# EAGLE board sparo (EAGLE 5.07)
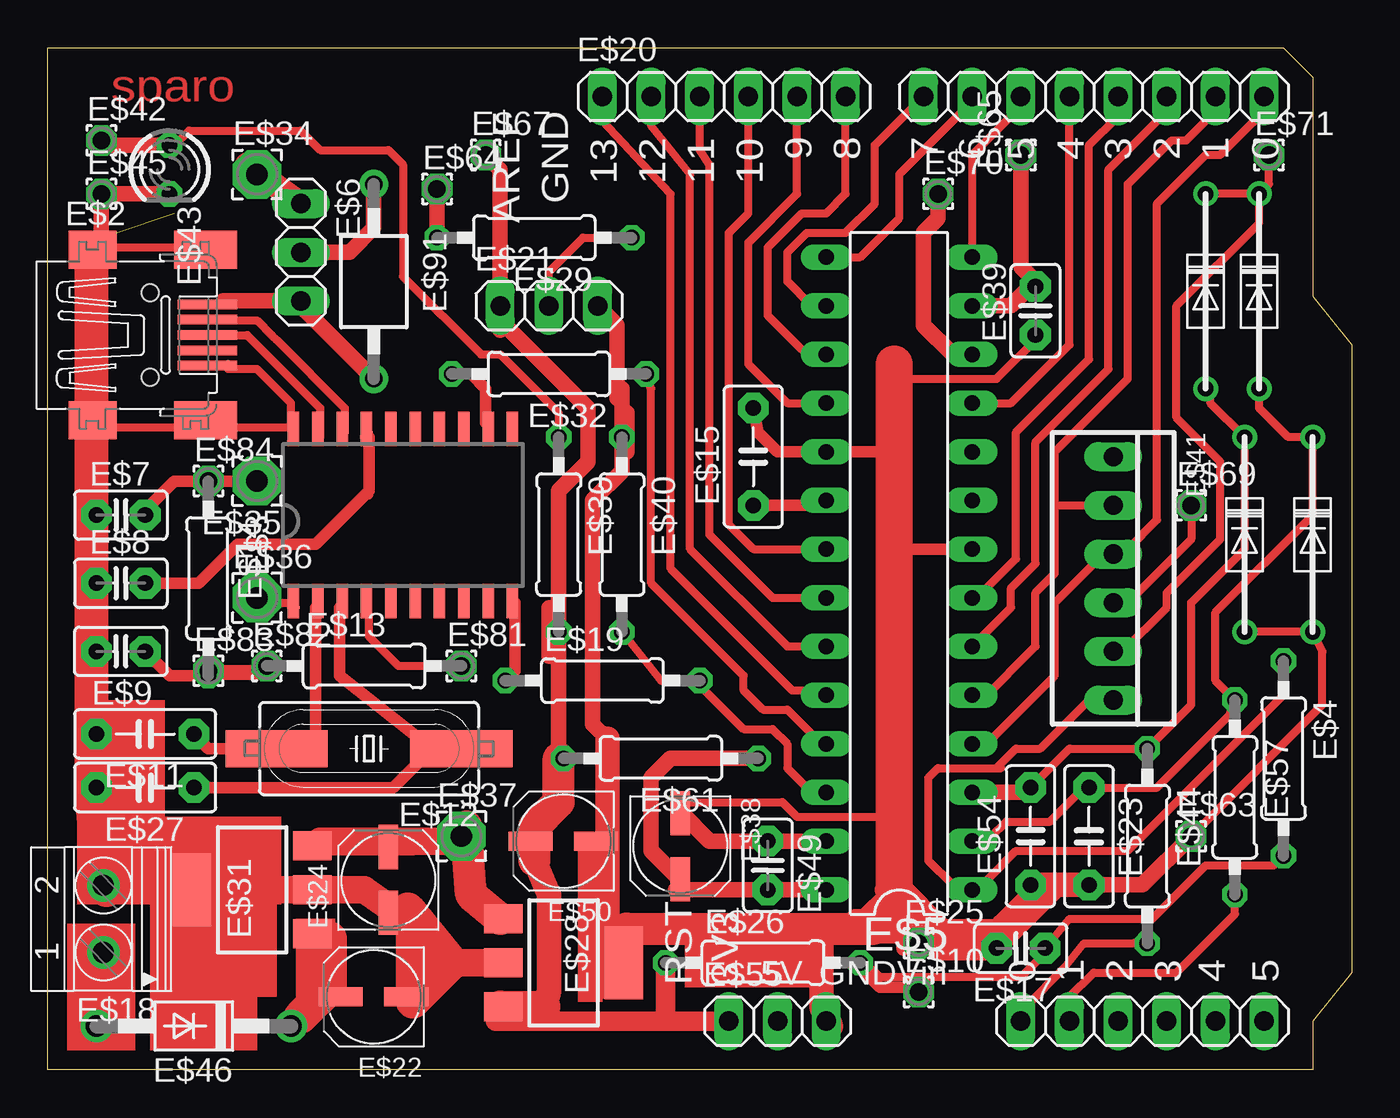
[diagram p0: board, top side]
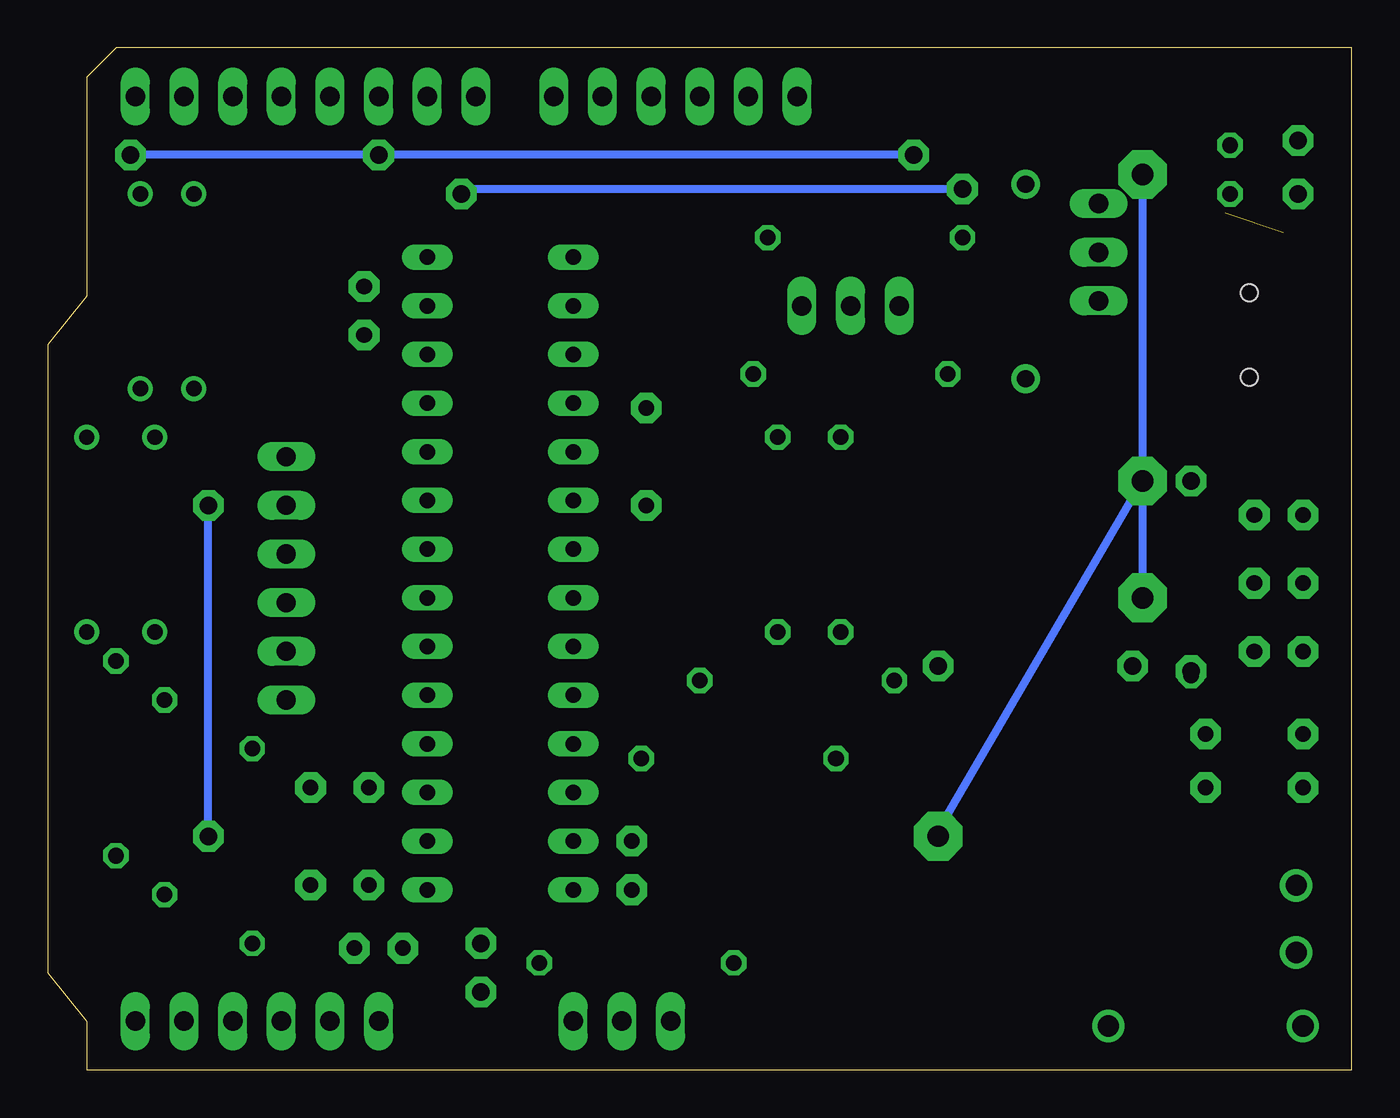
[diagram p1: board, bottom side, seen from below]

Size 68.07 x 53.34 mm. Coordinates in mm from the lower left corner, seen from the top.
Outline: 0,53.34 64.52,53.34 66.04,51.82 66.04,40.39 68.07,37.85 68.07,5.08 66.04,2.54 66.04,0 0,0 0,53.34
Copper layers (1*16): Top 0.035mm / dielectric 1.5mm / Bottom 0.035mm
Design rules "default": minimum track width 10mil, minimum drill 24mil, track to track 8mil, track to pad 8mil, pad to pad 8mil, via to via 8mil, smd to smd 8mil, copper to edge 40mil, drill to drill 8mil, minimum pad ring 10mil, minimum via ring 8mil, stop-mask expansion 4mil, vias tented up to drill 0mil, thermal gap 10mil

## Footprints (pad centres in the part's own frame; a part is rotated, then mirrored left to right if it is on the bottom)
32005-201 = smd 3.1 x 0.5: 1 3,1.6; 2 3,0.8; 3 3,0; 4 3,-0.8; 5 3,-1.6 | smd 2.5 x 2: M1 -3,-4.45; M2 -3,4.45 | smd 3.3 x 2: M3 2.9,4.45; M4 2.9,-4.45 | hole 0.9: 0,2.2; 0,-2.2
SOP20 = smd 0.6 x 1.8: 1 -5.715,-4.475; 2 -4.445,-4.475; 3 -3.175,-4.475; 4 -1.905,-4.475; 5 -0.635,-4.475; 6 0.635,-4.475; 7 1.905,-4.475; 8 3.175,-4.475; 9 4.445,-4.475; 10 5.715,-4.475; 11 5.715,4.5; 12 4.445,4.5; 13 3.175,4.5; 14 1.905,4.5; 15 0.635,4.5; 16 -0.635,4.5; 17 -1.905,4.5; 18 -3.175,4.5; 19 -4.445,4.5; 20 -5.715,4.5
0207/10 = drill 0.813 octagon: 1 -5.08,0; 2 5.08,0
DIL28-3 = drill 0.813 long: 1 -16.51,-3.81; 2 -13.97,-3.81; 3 -11.43,-3.81; 4 -8.89,-3.81; 5 -6.35,-3.81; 6 -3.81,-3.81; 7 -1.27,-3.81; 8 1.27,-3.81; 9 3.81,-3.81; 10 6.35,-3.81; 11 8.89,-3.81; 12 11.43,-3.81; 13 13.97,-3.81; 14 16.51,-3.81; 15 16.51,3.81; 16 13.97,3.81; 17 11.43,3.81; 18 8.89,3.81; 19 6.35,3.81; 20 3.81,3.81; 21 1.27,3.81; 22 -1.27,3.81; 23 -3.81,3.81; 24 -6.35,3.81; 25 -8.89,3.81; 26 -11.43,3.81; 27 -13.97,3.81; 28 -16.51,3.81
1X03 = drill 1.016 long: 1 -2.54,0; 2 0,0; 3 2.54,0
C2.5-2 = drill 0.813 pad 1.6 octagon: 1 -1.27,0; 2 1.27,0
1,6/0,9 = drill 0.914 pad 1.6 octagon: 1 0,0
C5B2.5 = drill 0.813 pad 1.6 octagon: 1 -2.54,0; 2 2.54,0
HC49UP = smd 5.334 x 1.93: 1 -4.826,0; 2 4.826,0
C5B3 = drill 0.813 pad 1.6 octagon: 1 -2.54,0; 2 2.54,0
1751248 = drill 1.1 pad 1.7 round: 1 -1.75,-0.1; 2 1.75,-0.1
1X06 = drill 1.016 long: 1 -6.35,0; 2 -3.81,0; 3 -1.27,0; 4 1.27,0; 5 3.81,0; 6 6.35,0
UD-5X5,8_NICHICON = smd 2.3 x 1: + 1.725,0; - -1.7,0
SOT223 = smd 1.5 x 2: 1 -2.3,-3.15; 2 0,-3.15; 3 2.3,-3.15 | smd 3.8 x 2: 4 0,3.15
DS10 = drill 0.8 round: P$1 -5.08,0; P$2 5.08,0
2,54/1,1 = drill 1.118 pad 2.54 octagon: 1 0,0
22-23-2061 = drill 1 long: 1 -6.35,0; 2 -3.81,0; 3 -1.27,0; 4 1.27,0; 5 3.81,0; 6 6.35,0
LED3MM = drill 0.813 octagon: A -1.27,0; K 1.27,0
DO41-10 = drill 1.118 round: A 5.08,0; C -5.08,0
BL01RN1A = drill 0.9 pad 1.5 round: 1 -5.08,0; 2 5.08,0
1X08 = drill 1.016 long: 1 -8.89,0; 2 -6.35,0; 3 -3.81,0; 4 -1.27,0; 5 1.27,0; 6 3.81,0; 7 6.35,0; 8 8.89,0

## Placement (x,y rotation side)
E$2  [32005-201]  5.33,38.35 0 top
E$3  [SOP20]  18.54,28.96 0 top
E$4  [0207/10]  64.52,16.26 270 top
E$5  [DIL28-3]  44.45,25.91 90 top
E$6  [1X03]  13.21,42.67 270 top
E$7  [C2.5-2]  3.81,28.96 0 top
E$8  [C2.5-2]  3.81,25.4 0 top
E$9  [C2.5-2]  3.81,21.84 180 top
E$10  [1,6/0,9]  45.47,4.06 0 top
E$11  [C5B2.5]  5.08,17.53 180 top
E$12  [HC49UP]  16.76,16.76 180 top
E$13  [0207/10]  16.51,21.08 0 top
E$14  [0207/10]  8.38,25.65 270 top
E$15  [C5B3]  36.83,32 90 top
E$17  [C2.5-2]  50.8,6.35 180 top
E$18  [1751248]  2.79,7.87 90 top
E$19  [0207/10]  28.96,20.32 0 top
E$20  [1X06]  35.31,50.8 0 top
E$21  [1X03]  26.16,39.88 0 top
E$22  [UD-5X5,8_NICHICON]  17.02,3.81 180 top
E$23  [C5B2.5]  54.36,12.19 270 top
E$24  [UD-5X5,8_NICHICON]  17.78,9.91 90 top
E$25  [1,6/0,9]  45.47,6.6 0 top
E$26  [0207/10]  37.34,5.59 0 top
E$27  [C5B2.5]  5.08,14.73 180 top
E$28  [SOT223]  26.92,5.59 270 top
E$29  [0207/10]  25.4,43.43 180 top
E$30  [0207/10]  26.67,27.94 270 top
E$31  [SOT223]  10.67,9.4 90 top
E$32  [0207/10]  26.16,36.32 180 top
E$33  [DS10]  63.25,40.64 90 top
E$34  [2,54/1,1]  10.92,46.74 0 top
E$35  [2,54/1,1]  10.92,30.73 180 top
E$36  [2,54/1,1]  10.92,24.64 0 top
E$37  [2,54/1,1]  21.59,12.19 0 top
E$38  [UD-5X5,8_NICHICON]  33.02,11.68 270 top
E$39  [C2.5-2]  51.56,39.62 90 top
E$40  [0207/10]  29.97,27.94 270 top
E$41  [22-23-2061]  55.63,25.65 270 top
E$42  [1,6/0,9]  2.79,48.51 0 top
E$43  [LED3MM]  6.35,46.99 270 top
E$44  [0207/10]  57.4,11.68 270 top
E$45  [1,6/0,9]  2.79,45.72 0 top
E$46  [DO41-10]  7.62,2.29 180 top
E$49  [C2.5-2]  37.59,10.67 270 top
E$50  [UD-5X5,8_NICHICON]  26.92,11.94 180 top
E$51  [DS10]  66.04,27.94 90 top
E$52  [DS10]  60.45,40.64 90 top
E$53  [DS10]  62.48,27.94 90 top
E$54  [C5B2.5]  51.31,12.19 90 top
E$55  [1X03]  38.1,2.54 0 top
E$57  [0207/10]  61.98,14.22 270 top
E$61  [0207/10]  32,16.26 180 top
E$63  [1,6/0,9]  59.69,12.19 0 top
E$64  [1,6/0,9]  20.32,45.97 0 top
E$65  [1,6/0,9]  50.8,47.75 90 top
E$67  [1,6/0,9]  22.86,47.75 0 top
E$69  [1,6/0,9]  59.69,29.46 0 top
E$70  [1,6/0,9]  46.48,45.72 0 top
E$71  [1,6/0,9]  63.75,47.75 0 top
E$81  [1,6/0,9]  21.59,21.08 0 top
E$82  [1,6/0,9]  11.43,21.08 0 top
E$83  [1,6/0,9]  8.38,20.83 0 top
E$84  [1,6/0,9]  8.38,30.73 0 top
E$91  [BL01RN1A]  17.02,41.15 270 top
U$2  ANALOG  [1X06]  57.15,2.54 0 top
U$3  DIGITAL_0_7  [1X08]  54.61,50.8 0 top

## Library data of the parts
E$2 = con-cypressindustries
E$3 = holtek
E$4 E$13 E$14 E$19 E$26 E$29 E$30 E$32 E$40 E$44 E$57 E$61 = resistor
E$5 = microchip
E$6 E$20 E$21 E$55 = pinhead
E$7-E$9 E$11 E$15 E$17 E$23 E$27 E$39 E$49 E$54 = capacitor-wima
E$10 E$25 E$34-E$37 E$42 E$45 E$63-E$65 E$67 E$69-E$71 E$81-E$84 = wirepad
E$12 = crystal
E$18 = con-phoenix-350
E$22 E$24 E$38 E$50 = rcl
E$28 E$31 = v-reg
E$33 E$51-E$53 = hydr
E$41 = con-molex
E$43 = led
E$46 = diode
E$91 = inductors
U$2 U$3 = arduino

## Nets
S$3: E$5.15
S$4: E$57.2
S$7: E$71.1
S$10: E$41.6
S$11: E$5.16 U$3.1
S$12: E$5.18
S$15: E$5.19 E$15.2
S$16: E$5.22 E$20.3
S$17: E$20.1
S$18: E$5.23 E$20.2
S$19: E$55.1
S$20: U$3.7
S$22: E$8.2
S$24: E$5.21
S$25: E$5.14
S$26: E$6.3 E$91.2
S$27: E$11.1
S$28: E$26.1
S$29: E$21.2 E$29.1
S$30: E$32.2
S$31: E$23.1
S$32: U$3.8
S$34: E$34.1 E$35.1
S$36: E$61.1
S$39: E$5.12 E$70.1
S$40: E$29.2 E$64.1
S$41: E$5.3 E$54.2
S$42: E$19.1
S$49: E$5.6
S$50: E$5.13
S$51: E$32.1
S$53: E$9.1 E$13.1
S$54: E$27.1
S$55: E$5.28 E$49.2
S$56: E$21.1 E$65.1 E$67.1
S$57: E$69.1
S$61: E$6.2 E$91.1
S$63: E$6.1
S$68: E$21.3
S$70: E$5.11 U$3.4
S$71: E$13.2
S$74: E$5.27
S$81: E$30.1
S$85: E$4.2
S$89: E$44.2
S$90: E$57.1
S$92: E$4.1
S$94: E$40.2
S$95: E$17.2 E$54.1
S$99: E$25.1
S$100: E$17.1
S$103: E$26.2

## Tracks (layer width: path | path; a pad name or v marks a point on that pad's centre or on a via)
S$1
  Top 0.406: 63.75,50.29 61.21,47.75 60.45,47.75 57.91,45.21 57.91,28.7 56.39,27.18
S$2
  Top 0.61: 13.97,24.13 13.97,17.53
S$3
  Top 0.406: E$5.15 42.42,42.42 44.45,44.45 44.45,46.74 48.26,50.55
S$4
  Top 0.406: 53.34,3.81 54.61,5.08 58.93,5.08 61.98,8.13 E$57.2
S$5
  Top 0.61: 42.42,5.33 43.43,4.32 45.72,4.32
S$6
  Top 0.813: 29.21,17.27 28.45,18.03 28.45,29.72 29.97,31.24 29.97,35.56
  Top 1.27: 29.21,4.32 29.21,17.27
S$7
  Top 0.406: E$71.1 63.75,46.23 63.25,45.72 | 63.25,45.72 63.25,45.97 | 63.25,45.72 60.71,45.72 | 63.25,45.72 63.25,44.2 58.93,39.88 58.93,34.04 61.21,31.75 61.21,27.69 58.42,24.89 58.42,24.13 56.13,21.84
S$8
  Top 0.406: 8.89,42.93 2.54,42.93 2.29,42.67
S$9
  Top 0.406: 55.88,49.78 54.36,48.26 54.36,37.08 50.55,33.27 50.55,26.67 48.77,24.89
S$10
  Top 0.406: 47.24,9.65 45.97,10.92 45.97,15.24 46.48,15.75 49.53,15.75 | 49.53,15.75 49.78,15.75 | 49.53,15.75 50.55,16.76 51.82,16.76 54.36,19.3 E$41.6
S$11
  Top 0.406: E$5.16 39.88,39.88 38.61,41.15 38.61,42.67 39.62,43.69 41.66,43.69 43.18,45.21 43.18,48.26 U$3.1 43.94,49.02
S$12
  Top 0.406: 39.12,50.8 39.12,45.72 36.58,43.18 36.58,36.83 38.61,34.8 E$5.18
S$13
  Top 0.406: 44.45,27.18 44.45,27.69
  Top 0.61: 44.45,27.18 48.51,27.18
S$14
  Top 0.305: 40.89,37.59 41.15,37.59
  Top 0.406: 41.66,50.55 41.66,45.72 40.64,44.7 39.37,44.7 37.59,42.93 37.59,39.37 39.37,37.59 40.89,37.59
S$15
  Top 0.406: E$5.19 44.45,32.26
  Top 0.61: E$15.2 37.08,33.27 38.1,32.26 E$5.19 43.69,32.26 43.94,32.51
S$16
  Top 0.406: E$5.22 37.85,24.64 34.54,27.94 34.54,47.24 34.04,48.01 E$20.3
S$17
  Top 0.406: 40.64,19.81 38.86,19.81 32.51,26.16 32.51,45.72 28.96,49.53 E$20.1
S$18
  Top 0.406: E$20.2 31.5,49.28 33.53,46.74 33.53,27.18 38.61,22.1 E$5.23
S$19
  Top 1.016: 23.37,2.54 E$55.1
S$20
  Top 0.406: 48.77,19.3 51.56,22.1 51.56,24.89 52.58,25.91 52.58,32.26 56.39,36.07 56.39,46.23 58.67,48.51 59.44,48.51 59.69,48.77 60.2,49.28 60.96,50.04 | 60.96,49.78 60.96,50.04 | U$3.7 60.96,50.55 60.96,50.04
S$21
  Top 0.61: 2.03,11.94 2.54,11.43
  Top 1.778: 2.29,14.48 2.29,42.93 | 2.29,14.48 2.54,14.48 | 2.54,11.43 2.29,14.48
S$22
  Top 0.406: 16.51,33.02 16.76,33.27 16.76,33.02 16.76,29.97
  Top 0.61: 16.76,33.02 16.76,30.23 13.97,27.43 9.91,27.43 7.87,25.4 E$8.2
S$23
  Top 0.406: 12.95,24.13 12.7,24.13 12.7,24.38 10.67,24.38
S$24
  Top 0.305: 35.56,42.16 35.56,34.8
  Top 0.406: 36.58,50.8 36.58,44.7 35.56,43.69 35.56,42.16 35.56,28.45 36.83,27.18 E$5.21
S$25
  Top 0.406: 50.8,50.29 48.26,47.75 E$5.14
S$26
  Top 0.813: 9.14,40.13 E$6.3 13.21,39.88 E$91.2
S$27
  Top 0.61: 13.97,17.02 14.22,16.76 8.38,16.76 E$11.1
S$28
  Top 1.016: 32.26,2.79 E$26.1
S$29
  Top 0.406: E$21.2 26.16,41.66 27.94,43.43 E$29.1
S$30
  Top 0.61: 22.86,33.78 22.86,35.56 22.1,36.32 E$32.2
S$31
  Top 0.406: 49.28,12.19 50.04,12.95 52.32,12.95 54.1,14.73 E$23.1
S$32
  Top 0.406: U$3.8 63.5,50.04 62.23,48.77
S$33
  Top 1.778: 14.73,6.86 14.73,4.32 13.21,2.79
S$34
  Bottom 0.406: 21.59,12.45 E$35.1 | E$35.1 10.92,24.38 | E$34.1 E$35.1
S$35
  Top 1.676: 30.23,7.37 43.18,7.37 44.2,8.38
S$36
  Top 0.813: E$61.1 32.51,16.26 31.5,15.24 31.5,11.68 31.5,11.43 33.02,9.91
S$37
  Top 0.406: 52.58,29.46 55.63,29.46
S$38
  Top 1.778: 2.54,12.19 2.54,11.94 3.05,9.4
S$39
  Top 0.813: E$5.12 47.24,37.34 45.72,38.86 45.72,43.69 46.48,44.45 E$70.1
S$40
  Top 0.813: E$29.2 E$64.1
  Bottom 0.406: E$64.1 46.48,45.97
S$41
  Top 0.406: 57.4,16.76 53.34,16.76 52.32,15.75 51.82,15.24 E$54.2
  Top 0.813: E$5.3 51.05,14.48 E$54.2
S$42
  Top 0.61: 24.38,24.38 24.38,20.83 E$19.1
S$43
  Top 1.27: 40.39,7.11 40.39,3.3 40.89,2.29
S$44
  Top 0.813: 2.54,45.72 6.6,45.72
S$46  (1 unrouted)
S$47
  Top 0.406: 54.61,26.42 52.58,24.38 52.58,20.57 49.02,17.02
S$48
  Top 0.406: 45.21,36.07 49.53,36.07 51.82,38.35
S$49
  Top 0.406: 58.42,50.04 55.37,46.99 55.37,36.58 51.56,32.77 51.56,26.42 50.29,25.15 50.29,24.13 E$5.6
S$50
  Top 0.813: 51.31,40.89 50.29,39.88 E$5.13
S$51
  Top 0.406: E$32.1 31.5,35.56 31.5,25.4 36.32,20.57 36.32,19.81 37.34,18.8 38.61,18.8 40.39,17.02
S$52
  Top 0.406: 44.2,8.13 43.94,7.62
S$53
  Top 0.406: E$13.1 10.92,20.57 8.38,20.57
  Top 0.61: E$9.1 6.35,20.57 8.38,20.57 8.64,20.83 11.43,20.83
S$54
  Top 0.61: E$27.1 18.03,14.73 19.56,16.26
S$55
  Top 0.813: E$5.28 E$49.2 32.77,9.4
S$56
  Top 0.813: 51.82,40.89 50.8,41.91 E$65.1 | E$67.1 23.62,46.99 E$21.1 | E$21.1 23.62,38.61 | E$21.1 23.62,40.13 | E$21.1 23.62,39.12 28.19,34.54 28.19,31.75 26.67,30.23 26.67,16.26
  Top 1.27: 25.4,10.92 26.16,9.14 26.16,4.06 25.91,3.3
  Top 1.676: 26.67,16.26 26.67,13.97 25.4,12.7 25.4,10.92 | 23.62,3.3 25.91,3.3
  Bottom 0.406: 64.01,47.75 E$65.1 E$67.1
S$57
  Top 0.406: 56.64,24.38 56.64,24.64 59.69,27.69 E$69.1
  Bottom 0.406: 59.69,12.19 E$69.1
S$58
  Top 0.406: 14.73,7.11 14.48,6.86
S$59
  Top 0.406: 19.05,11.68 19.3,11.68
  Top 1.016: 14.48,11.68 19.05,11.68
S$60
  Top 0.61: 11.94,16.76 13.72,17.02
S$61
  Top 0.813: E$91.1 17.02,43.94 15.75,42.67 E$6.2
S$62
  Top 0.61: 15.24,24.13 15.24,20.57 20.07,16.76
S$63
  Top 1.27: E$6.1 10.41,47.24
S$64
  Top 0.406: 2.03,33.53 9.4,33.53 9.14,33.78
S$65
  Top 0.406: 12.7,33.53 12.7,34.8 11.43,36.07 10.92,36.58 9.4,36.58 9.4,36.83 | 12.7,33.53 12.7,32.77 | 9.65,33.53 12.7,33.53
S$66
  Top 0.406: 14.22,33.02 14.22,34.54 10.41,38.35 9.4,38.35
S$67
  Top 0.406: 15.49,33.27 15.49,34.54 11.94,38.1 11.68,38.35 10.92,39.12 9.65,39.12
S$68
  Top 0.813: 29.46,39.12 E$21.3 29.72,38.86 29.72,35.05
S$69
  Top 1.422: 14.22,11.94 21.84,11.94
S$70
  Top 0.406: E$5.11 50.29,34.8 53.34,37.85 U$3.4
S$71
  Top 0.406: 16.76,23.62 16.76,22.61 18.29,21.08 E$13.2
S$72
  Top 0.406: 10.92,30.73 9.14,30.73
  Top 0.61: 4.83,28.96 6.6,30.73 10.92,30.73
S$73
  Top 0.406: 2.29,42.42 2.54,42.67 | 2.29,34.04 2.54,33.78
  Top 0.813: 2.29,34.04 2.29,42.42
S$74
  Top 0.813: E$5.27 34.54,11.94 33.02,13.46
S$75
  Top 0.813: 26.16,24.13 26.16,21.59
S$76
  Top 1.676: 21.84,12.7 22.1,9.14 23.62,7.87
S$77
  Top 0.406: 43.43,13.21 39.12,13.21 38.35,13.97 33.02,13.97
S$78
  Top 0.406: 51.05,3.3 53.09,5.33 54.1,6.6 57.66,6.6
S$79
  Top 0.813: 30.23,34.29 30.23,32.26
S$80
  Top 0.61: 40.89,29.72 39.88,29.46 36.83,29.46
S$81
  Top 0.406: E$30.1 26.67,34.29 23.62,37.34 22.61,37.34 18.54,41.4 18.54,47.24 17.78,48.01 14.22,48.01 13.21,49.02 7.37,49.02 6.6,48.26
S$82
  Top 0.406: 8.13,8.89 8.38,9.14
S$83
  Top 1.016: 43.43,7.37 50.29,7.37
S$84
  Top 1.422: 21.08,5.59 23.37,5.59 | 19.05,7.62 16.51,9.4 9.14,9.4
  Top 1.778: 18.8,8.38 21.08,5.59 19.05,3.56 19.05,7.62
S$85
  Top 0.406: 53.59,7.87 57.66,7.87 60.45,10.67 64.01,10.67 E$4.2
S$86
  Top 0.813: 2.79,48.26 6.35,48.26
S$87
  Top 0.406: 2.29,18.03 2.54,18.29
S$88
  Top 0.406: 8.64,8.89 8.89,8.89
S$89
  Top 0.406: E$44.2 56.64,6.6
S$90
  Top 0.406: 63.25,35.81 63.25,34.54 64.77,33.02 66.04,33.02 66.04,28.96 60.96,23.88 60.96,20.32 E$57.1 61.72,18.54 57.91,14.73 54.61,14.73
S$91
  Top 1.016: 49.78,7.62 51.56,9.4
S$92
  Top 0.406: 49.02,9.91 50.55,11.43 56.39,11.43 64.52,19.56 E$4.1
S$93
  Top 0.813: 2.79,43.43 2.79,44.96
S$94
  Top 0.406: 39.88,14.48 38.61,15.75 38.61,17.02 37.85,17.78 36.32,17.78 33.78,20.32 32,20.32 E$40.2
S$95
  Top 0.406: 62.48,22.86 66.04,22.86 66.55,21.84 66.55,19.05 59.69,12.19
  Top 0.813: 59.69,12.19 57.15,9.65 54.36,9.65 54.61,9.4 | E$17.2 49.53,6.86 | 46.48,6.35 45.72,6.86 44.7,6.35
  Top 1.016: E$17.2 52.83,9.65
  Top 1.27: 54.36,9.65 E$54.1 52.83,9.65 | 46.48,6.35 E$17.2
S$96
  Top 0.406: 60.71,35.56 60.71,34.8 62.48,33.02 62.48,27.18 59.69,24.38 59.69,19.05 57.4,16.76
S$97
  Top 0.813: 44.7,6.6 44.7,8.38
S$98
  Top 1.016: 44.45,8.89 46.23,7.11
S$99
  Top 1.016: E$25.1 44.96,7.11 43.18,7.11
S$100
  Top 0.406: 55.12,7.87 53.34,7.87 E$17.1
S$101
  Top 0.406: 44.96,4.06 45.97,4.06
S$102
  Top 1.016: 44.45,9.65 46.74,7.37 46.74,7.11
S$103
  Top 0.406: 52.32,6.35 50.8,4.83 43.43,4.83 42.67,5.59 E$26.2 43.18,4.83
S$104
  Top 1.016: 44.2,9.4 43.69,9.4
  Top 1.27: 44.2,8.64 43.94,8.64
  Top 1.93: 44.2,8.64 44.2,9.4 44.2,36.83
S$105
  Top 1.016: 43.94,9.14 42.67,7.87 42.16,7.87
S$111
  Top 0.406: 29.21,4.32 28.96,4.32
(copper drawn outside any net)
  shapes: Top area x8

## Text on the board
Top: sparo
tNames: 9 | 8 | 7 | 6 | 5 | 4 | 3 | 2 | 1 | 0 | 13 | 12 | 11 | 10 | GND | AREF | 0 | 1 | 2 | 3 | 4 | 5 | RST | 3V3 | 5V | GND | Vin
TallParts: USB
ArduinoHoles: 3.2mm | 2.2mm | 3.2mm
